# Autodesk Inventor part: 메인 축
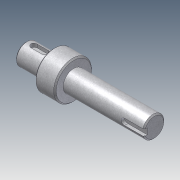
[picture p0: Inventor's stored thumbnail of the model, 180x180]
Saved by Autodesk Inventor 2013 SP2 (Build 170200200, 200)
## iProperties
Company: 한국ATC센터
Created: 2014-10
Part Number: 메인 축
Document SubType Name: Modeling
Designer: KYOUNG IL JANG
Density: 1 g/cm^3
Mass: 29.2926 g
Surface Area: 74.3518 cm^2
Volume: 29.2926 cm^3
Material: 일반
Author: KYOUNG IL JANG
Revision Number: 1
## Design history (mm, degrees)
sketch "스케치1"
  geometry: L1 (10.497, -57.5)-(112.497, -57.5); L2 (10.497, -66)-(32.497, -66); L3 (32.497, -72.5)-(46.5, -72.5); L4 (46.5, -66)-(112.497, -66); L5 (112.497, -66)-(112.497, -57.5); L6 (10.497, -66)-(10.497, -57.5); L7 (46.5, -69.749)-(46.5, -45.251) reference; L8 (46.5, -72.5)-(46.5, -66); L9 (32.497, -72.5)-(32.497, -66); L10 (32.497, -35)-(32.497, -80) reference; 3 further points
  constraints: 16 end point, 3 point on line, 2 parallel, 2 perpendicular, 1 collinear, 1 horizontal, 1 midpoint
  dimensions: "d0" = 17 diameter of L4 L1; "d1" = 30 diameter of L3 L1; "d2" = 22 distance of L2.start L2.end; "d3" = 65.99692 distance of L4.start L4.end (derived); "d5" = 17 diameter of L2 L1; "d19" = 80 distance between parallel lines of L5 L9
revolve "회전1" sketch "스케치1" stored, may be unused: angle "d4" = 90 deg
chamfer "모따기1" distance "d6" = 1; stored, may be unused: second distance "d7" = 2, angle "d8" = 45 deg
node "작업 평면1"
sketch "스케치2"
  geometry: L1 (-11, -7.5)-(-11, 7.5) reference; L2 (-4.5, 2.5)-(4.5, 2.5); L3 (4.5, -2.5)-(-4.5, -2.5); A1 r 2.5 centre (4.5, 0) between (4.5, -2.5) and (4.5, 2.5); A2 r 2.5 centre (-4.5, 0) between (-4.5, 2.5) and (-4.5, -2.5); 2 further points
  constraints: 4 end point, 4 point on circle, 4 tangent, 2 centre point, 1 horizontal alignment, 1 midpoint, 1 parallel, 1 perpendicular
  dimensions: "d9" = 5 distance between parallel lines of L3 L2; "d10" = 14 dimension on A1 A2; "d11" = 4 distance edge to line of A2 L1
extrude "돌출1" cut sketch "스케치2" distance "d12" = 3; taper "d13" = 0 deg
node "작업 평면2"
sketch "스케치3"
  geometry: L1 (32.998, 7.5)-(32.998, -7.5) reference; L2 (32.998, 2.5)-(17.498, 2.5); L3 (17.498, -2.5)-(32.998, -2.5); A1 r 2.5 centre (17.498, 0) between (17.498, 2.5) and (17.498, -2.5); 2 further points
  constraints: 4 end point, 2 perpendicular, 2 point on circle, 2 point on line, 2 tangent, 1 centre point, 1 horizontal alignment, 1 midpoint
  dimensions: "d14" = 5 distance between parallel lines of L3 L2; "d15" = 18 dimension on A1 L1
extrude "돌출2" cut sketch "스케치3" distance "d16" = 3; taper "d17" = 0 deg
node "솔리드1"
node "참조4"
node "참조5"
